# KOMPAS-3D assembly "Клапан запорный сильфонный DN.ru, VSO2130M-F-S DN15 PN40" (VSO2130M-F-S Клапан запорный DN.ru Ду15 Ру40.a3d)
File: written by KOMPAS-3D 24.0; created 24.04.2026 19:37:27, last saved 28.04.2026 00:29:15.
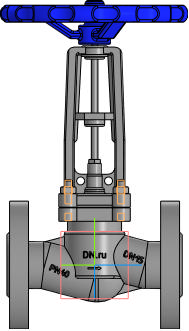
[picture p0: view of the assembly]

Document properties: Автор: DN.ru; Полное имя файла: C:\Работа\ГОТОВЫЕ ИСХОДНИКИ\VSO2130M-F-S Клапан запорный сильфонный DN.ru Ду15-100 Ру40\исходные материалы\DN15\VSO2130M-F-S Клапан запорный DN.ru Ду15 Ру40.a3d

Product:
- Component [detail]: Корпус  | qty 1  | pos. 1  | Масса: 6.9; Автор: R2D2; source file: Korpus.m3d
- Component [detail]: Деталь  | qty 1  | pos. 2  | Масса: 0.451515; Автор: mrdid; source file: rama.m3d
- Component [detail]: Деталь2  | qty 1  | pos. 3  | Масса: 0.594157; Автор: R2D2; additional columns: Типовые; source file: shturval.m3d
- Component [standard]: Шпилька М6-6gx25 ГОСТ 22032-76  | qty 4  | Масса: 0.005789; Раздел спецификации: Стандартные изделия; Рассекать на разрезах: no
- Component [standard]: Гайка М6-6H ГОСТ 5915-70  | qty 4  | Масса: 0.002573; Раздел спецификации: Стандартные изделия; Рассекать на разрезах: no
- Part/product: Клапан запорный сильфонный DN.ru  | designation VSO2130M-F-S DN15 PN40
    Масса: 4
    Раздел спецификации: Прочие изделия
    Примечание: D090-01970

Referenced files in C:\Работа\ГОТОВЫЕ ИСХОДНИКИ\VSO2130M-F-S Клапан запорный сильфонный DN.ru Ду15-100 Ру40\исходные материалы\DN15\: Korpus.m3d, rama.m3d, shturval.m3d
Referenced files in C:\Program Files\ASCON\KOMPAS-3D v24\Libs\PolynomLib\DATA\vault\Methods\Kompas\3D\: PLib_Stud_1_900.m3d, PLib_Nut_OST92_900.m3d
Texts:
  Крепежное изделие ГОСТ
  BOSimple***PART:e489ae6d-d315-b2e9-dd59-4407119351be***SHORTLOC:Root±30±20±10±120±10±20[Нет;Без покрытия;Без указания материала;-;6;25;1;1]
  BOSimple***PART:832b7c99-94b5-75d7-382c-73b3a2f1c6df***SHORTLOC:Root±30±10±20±©{}110±10±50±60[Нет;Без покрытия;Без указания материала;-;6;1;10]
  Программные изделия  и базы данных
  VSO2130M-F-S DN15 PN40
  Деталь2 Деталь2
  Шпилька М6-6gx25 ГОСТ 22032-76 (1)
  cut1
  Шпилька М6-6gx25 ГОСТ 22032-76 (2)
  Шпилька М6-6gx25 ГОСТ 22032-76 (3)
  Шпилька М6-6gx25 ГОСТ 22032-76 (4)
  Гайка М6-6H ГОСТ 5915-70 (1)
  bcut1
  hole1
  hcut1
  hole2
  Гайка М6-6H ГОСТ 5915-70 (2)
  Гайка М6-6H ГОСТ 5915-70 (3)
  Гайка М6-6H ГОСТ 5915-70 (4)
  Плоскость XY.Начало координат
  Грань.Элемент выдавливания:2.Экземпляр ( 2, 1 )
  Plane. Начало координат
